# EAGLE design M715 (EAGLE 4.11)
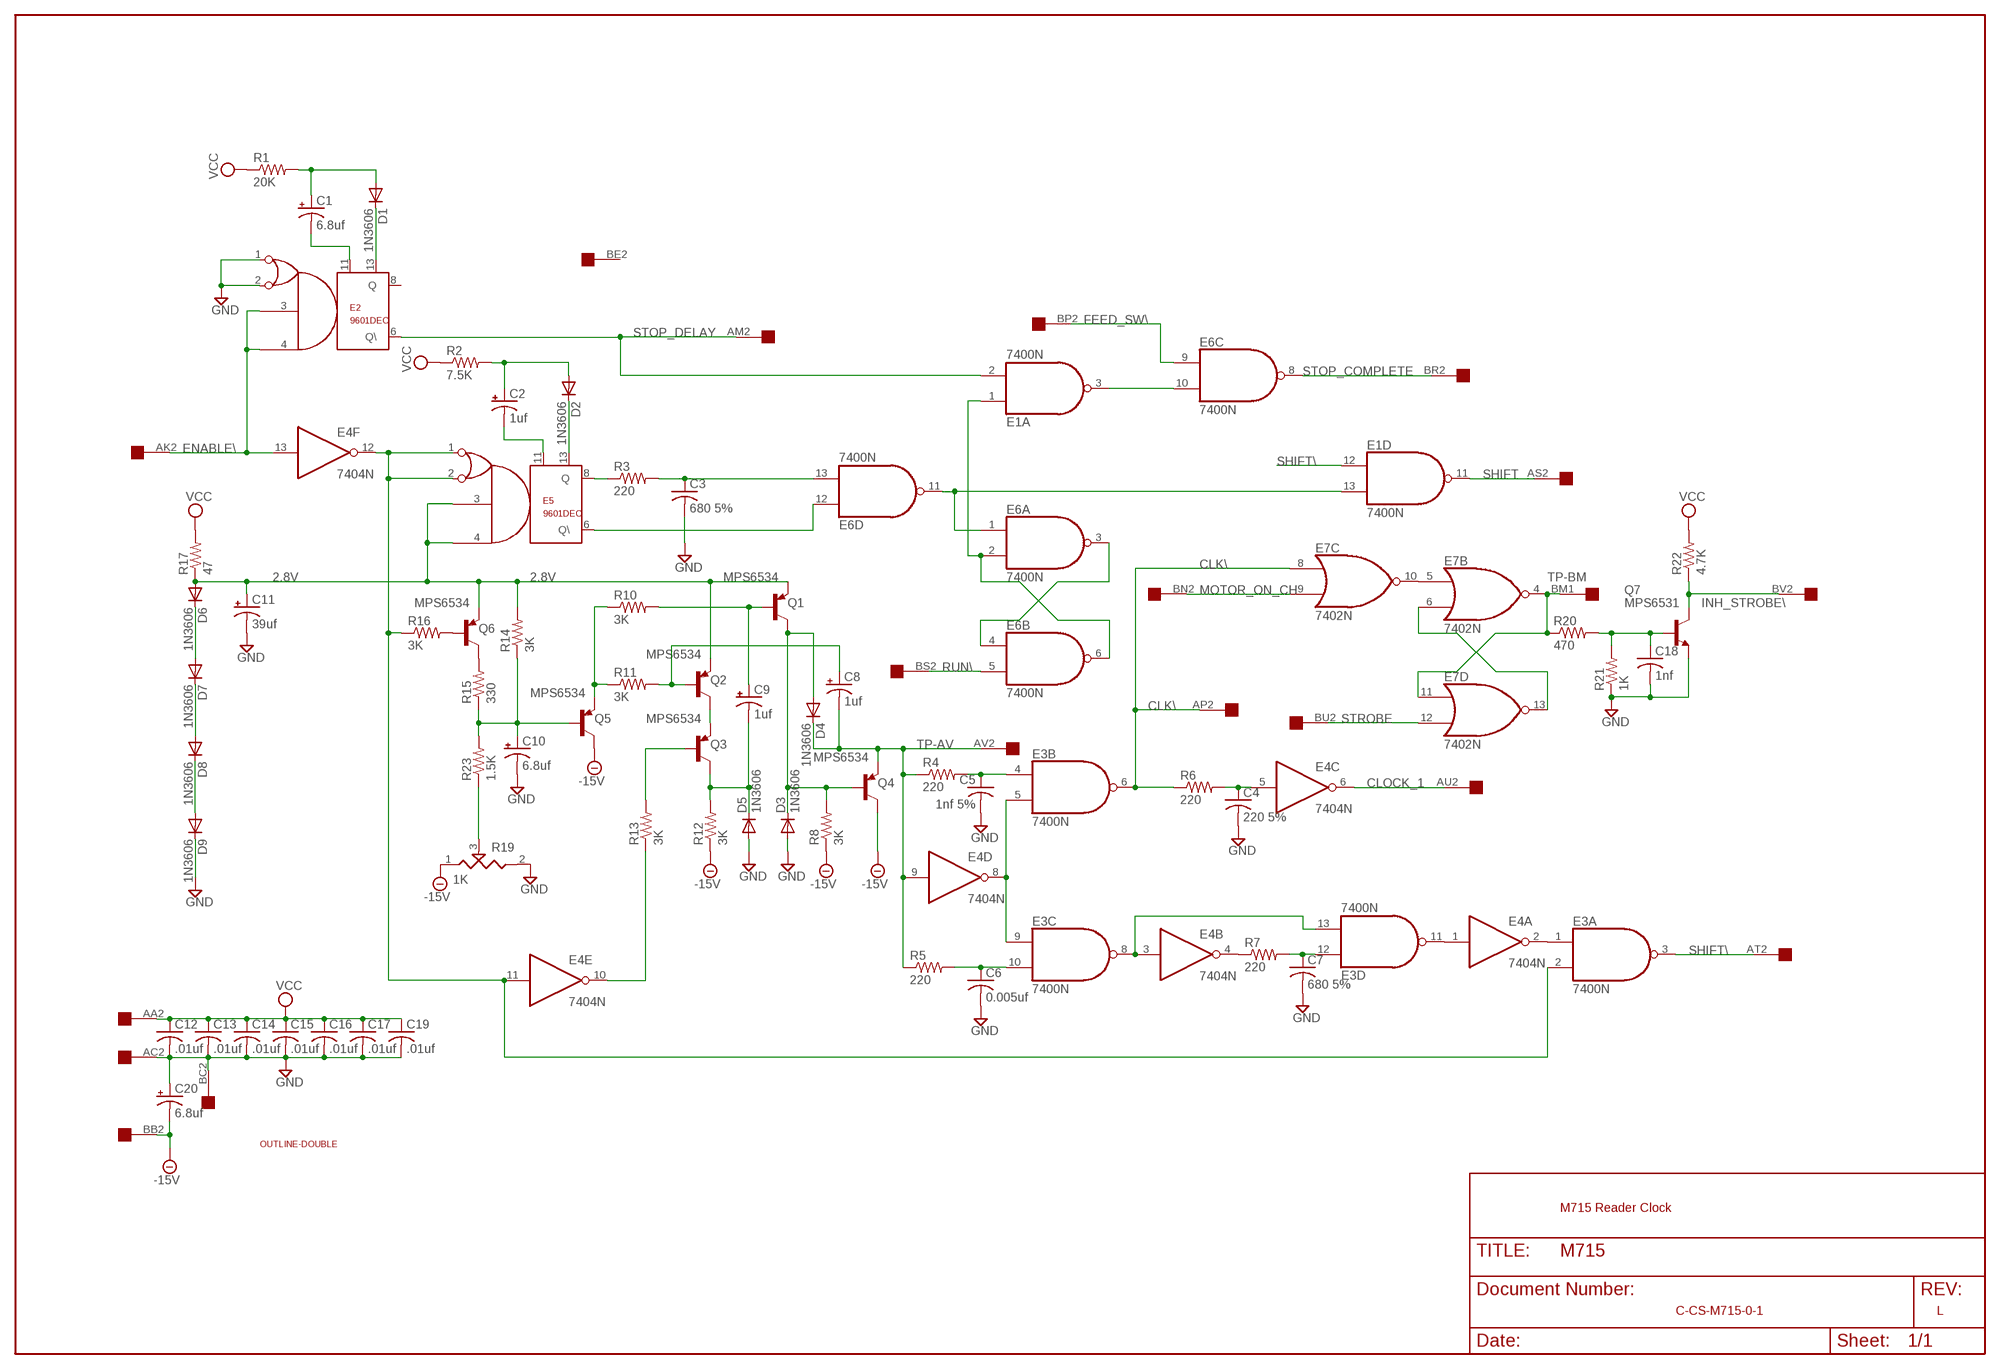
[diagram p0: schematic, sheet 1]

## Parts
C1  6.8uf  CPOL-USE22-6AXIAL  [E22-6]
C2  1uf  CPOL-USE15-5AXIAL  [E15-5]
C3  680 5%  C-US050-025X075  [C050-025X075]
C4  220 5%  C-US050-025X075  [C050-025X075]
C5  1nf 5%  C-US050-025X075  [C050-025X075]
C6  0.005uf  C-US050-025X075  [C050-025X075]
C7  680 5%  C-US050-025X075  [C050-025X075]
C8  1uf  CPOL-USE15-5AXIAL  [E15-5]
C9  1uf  CPOL-USE15-5AXIAL  [E15-5]
C10  6.8uf  CPOL-USE22-6AXIAL  [E22-6]
C11  39uf  CPOL-USE22-6AXIAL  [E22-6]
C12  .01uf  C-US050-025X075  [C050-025X075]
C13  .01uf  C-US050-025X075  [C050-025X075]
C14  .01uf  C-US050-025X075  [C050-025X075]
C15  .01uf  C-US050-025X075  [C050-025X075]
C16  .01uf  C-US050-025X075  [C050-025X075]
C17  .01uf  C-US050-025X075  [C050-025X075]
C18  1nf  C-US050-025X075  [C050-025X075]
C19  .01uf  C-US050-025X075  [C050-025X075]
C20  6.8uf  CPOL-USE22-6AXIAL  [E22-6]
D1  1N3606  1N4148  [DO35-10]
D2  1N3606  1N4148  [DO35-10]
D3  1N3606  1N4148  [DO35-10]
D4  1N3606  1N4148  [DO35-10]
D5  1N3606  1N4148  [DO35-10]
D6  1N3606  1N4148  [DO35-10]
D7  1N3606  1N4148  [DO35-10]
D8  1N3606  1N4148  [DO35-10]
D9  1N3606  1N4148  [DO35-10]
E1  7400N  [DIL14]
E2  9601DEC  [DIL14]
E3  7400N  [DIL14]
E4  7404N  [DIL14]
E5  9601DEC  [DIL14]
E6  7400N  [DIL14]
E7  7402N  [DIL14]
Q1  MPS6534  -PNP-TO92  [TO92]
Q2  MPS6534  -PNP-TO92  [TO92]
Q3  MPS6534  -PNP-TO92  [TO92]
Q4  MPS6534  -PNP-TO92  [TO92]
Q5  MPS6534  -PNP-TO92  [TO92]
Q6  MPS6534  -PNP-TO92  [TO92]
Q7  MPS6531  -NPN-TO92  [TO92]
R1  20K  R-US_0207/10  [0207/10]
R2  7.5K  R-US_0207/10  [0207/10]
R3  220  R-US_0207/10  [0207/10]
R4  220  R-US_0207/10  [0207/10]
R5  220  R-US_0207/10  [0207/10]
R6  220  R-US_0207/10  [0207/10]
R7  220  R-US_0207/10  [0207/10]
R8  3K  R-US_0207/10  [0207/10]
R10  3K  R-US_0207/10  [0207/10]
R11  3K  R-US_0207/10  [0207/10]
R12  3K  R-US_0207/10  [0207/10]
R13  3K  R-US_0207/10  [0207/10]
R14  3K  R-US_0207/10  [0207/10]
R15  330  R-US_0207/10  [0207/10]
R16  3K  R-US_0207/10  [0207/10]
R17  47  R-US_0207/10  [0207/10]
R19  1K  POTUS-TRIM  [PT-SPIN]
R20  470  R-US_0207/10  [0207/10]
R21  1K  R-US_0207/10  [0207/10]
R22  4.7K  R-US_0207/10  [0207/10]
R23  1.5K  R-US_0207/10  [0207/10]
U$1  DOUBLE  [EDGE-CON4]
U$2  OUTLINE-DOUBLE  [DOUBLE]

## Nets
2.8V: C11.+ D6.A E5.3 E5.4 Q1.1(E) Q2.1(E) Q6.1(E) R14.2 R17.1
-15V: C20.- Q4.3(C) Q5.3(C) R8.1 R12.1 R19.1 U$1.BB2
CLK\: E3.6(B:O) E7.8(C:I0) R6.1 U$1.AP2
CLOCK_1: E4.6(C:O) U$1.AU2
ENABLE\: E2.3 E2.4 E4.13(F:I) U$1.AK2
FEED_SW\: E6.9(C:I0) U$1.BP2
GND: C3.2 C4.2 C5.2 C6.2 C7.2 C10.- C11.- C12.2 C13.2 C14.2 C15.2 C16.2 C17.2 C18.2 C19.2 C20.+ D3.A D5.A D9.C E2.1 E2.2 Q7.1(E) R19.2 R21.1 U$1.AC2 U$1.BC2
INH_STROBE\: Q7.3(C) R22.1 U$1.BV2
MOTOR_ON_CH: E7.9(C:I1) U$1.BN2
N$1: E6.3(A:O) E6.4(B:I0)
N$2: E1.1(A:I0) E6.2(A:I1) E6.6(B:O)
N$3: E1.13(D:I1) E6.1(A:I0) E6.11(D:O)
N$4: E3.1(A:I0) E4.2(A:O)
N$5: E7.6(B:I1) E7.13(D:O)
N$6: E1.3(A:O) E6.10(C:I1)
N$7: Q6.2(B) R16.2
N$8: E7.5(B:I0) E7.10(C:O)
N$9: E3.2(A:I1) E4.11(E:I) E4.12(F:O) E5.1 E5.2 R16.1
N$10: E3.5(B:I1) E3.9(C:I0) E4.8(D:O)
N$11: E3.11(D:O) E4.1(A:I)
N$12: E3.8(C:O) E3.13(D:I1) E4.3(B:I)
N$13: C7.1 E3.12(D:I0) R7.2
N$14: E4.4(B:O) R7.1
N$15: R19.3 R23.1
N$16: C4.1 E4.5(C:I) R6.2
N$17: C18.1 Q7.2(B) R20.2 R21.2
N$18: C6.1 E3.10(C:I1) R5.2
N$19: C5.1 E3.4(B:I0) R4.2
N$20: D6.C D7.A
N$21: D7.C D8.A
N$22: D8.C D9.A
N$23: Q6.3(C) R15.2
N$24: C10.+ Q5.2(B) R14.1 R15.1 R23.2
N$26: Q5.1(E) R10.1 R11.1
N$27: Q2.3(C) Q3.1(E)
N$28: C8.+ Q2.2(B) R11.2
N$29: E4.10(E:O) R13.1
N$30: Q3.2(B) R13.2
N$31: C9.- D5.C Q3.3(C) R12.2
N$32: C9.+ Q1.2(B) R10.2
N$33: D3.C D4.A Q1.3(C) Q4.2(B) R8.2
N$35: D1.C E2.13
N$36: C1.- E2.11
N$37: C1.+ D1.A R1.2
N$38: D2.C E5.13
N$39: C2.- E5.11
N$40: C2.+ D2.A R2.2
N$41: E5.6(Q\) E6.12(D:I0)
N$42: E5.8(Q) R3.1
N$43: C3.1 E6.13(D:I1) R3.2
RUN\: E6.5(B:I1) U$1.BS2
SHIFT: E1.11(D:O) U$1.AS2
SHIFT\: E1.12(D:I0) E3.3(A:O) U$1.AT2
STOP_COMPLETE: E6.8(C:O) U$1.BR2
STOP_DELAY: E1.2(A:I1) E2.6(Q\) U$1.AM2
STROBE: E7.12(D:I1) U$1.BU2
TP-AV: C8.- D4.C E4.9(D:I) Q4.1(E) R4.1 R5.1 U$1.AV2
TP-BM: E7.4(B:O) E7.11(D:I0) R20.1 U$1.BM1
VCC: C12.1 C13.1 C14.1 C15.1 C16.1 C17.1 C19.1 R1.1 R2.1 R17.2 R22.2 U$1.AA2
Unconnected: E1.4(B:I0) E1.5(B:I1) E1.6(B:O) E1.8(C:O) E1.9(C:I0) E1.10(C:I1) E2.8(Q) E7.1(A:O) E7.2(A:I0) E7.3(A:I1) U$1.AA1 U$1.AB1 U$1.AB2 U$1.AC1 U$1.AD1 U$1.AD2 U$1.AE1 U$1.AE2 U$1.AF1 U$1.AF2 U$1.AH1 U$1.AH2 U$1.AJ1 U$1.AJ2 U$1.AK1 U$1.AL1 U$1.AL2 U$1.AM1 U$1.AN1 U$1.AN2 U$1.AP1 U$1.AR1 U$1.AR2 U$1.AS1 U$1.AT1 U$1.AU1 U$1.AV1 U$1.BA1 U$1.BA2 U$1.BB1 U$1.BC1 U$1.BD1 U$1.BD2 U$1.BE1 U$1.BE2 U$1.BF1 U$1.BF2 U$1.BH1 U$1.BH2 U$1.BJ1 U$1.BJ2 U$1.BK1 U$1.BK2 U$1.BL1 U$1.BL2 U$1.BM2 U$1.BN1 U$1.BP1 U$1.BR1 U$1.BS1 U$1.BT1 U$1.BT2 U$1.BU1 U$1.BV1

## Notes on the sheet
- M715 Reader Clock
- C-CS-M715-0-1 | L

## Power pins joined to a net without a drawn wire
GND: E1.7(P:GND) E2.7(GND) E3.7(P:GND) E4.7(P:GND) E5.7(GND) E6.7(P:GND) E7.7(P:GND)
VCC: E1.14(P:VCC) E2.14(VCC) E3.14(P:VCC) E4.14(P:VCC) E5.14(VCC) E6.14(P:VCC) E7.14(P:VCC)

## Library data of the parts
C1 C2 C8-C11 C20 = rcl:CPOL-US: POLARIZED CAPACITOR, American symbol
C3-C7 C12-C19 = rcl:C-US: CAPACITOR, American symbol
D1-D9 = diode:1N4148: DIODE
E1 E3 E6 = 74xx-us:74*00: Quad 2-input NAND gate
E2 E5 = dec-con:9601
E4 = 74xx-us:74*04: Hex INVERTER
E7 = 74xx-us:74*02: Quad 2-input NOR gate
Q1-Q6 = transistor:*-PNP-: PNP Transistror
Q7 = transistor:*-NPN-: NPN Transistror
R1-R8 R10-R17 R20-R23 = rcl:R-US_: RESISTOR, American symbol
R19 = discrete:POTUS-TRIM
U$1 = dec-con:DOUBLE: Double-Height DEC board
U$2 = dec-con:OUTLINE-*: Board outlines for DEC boards.

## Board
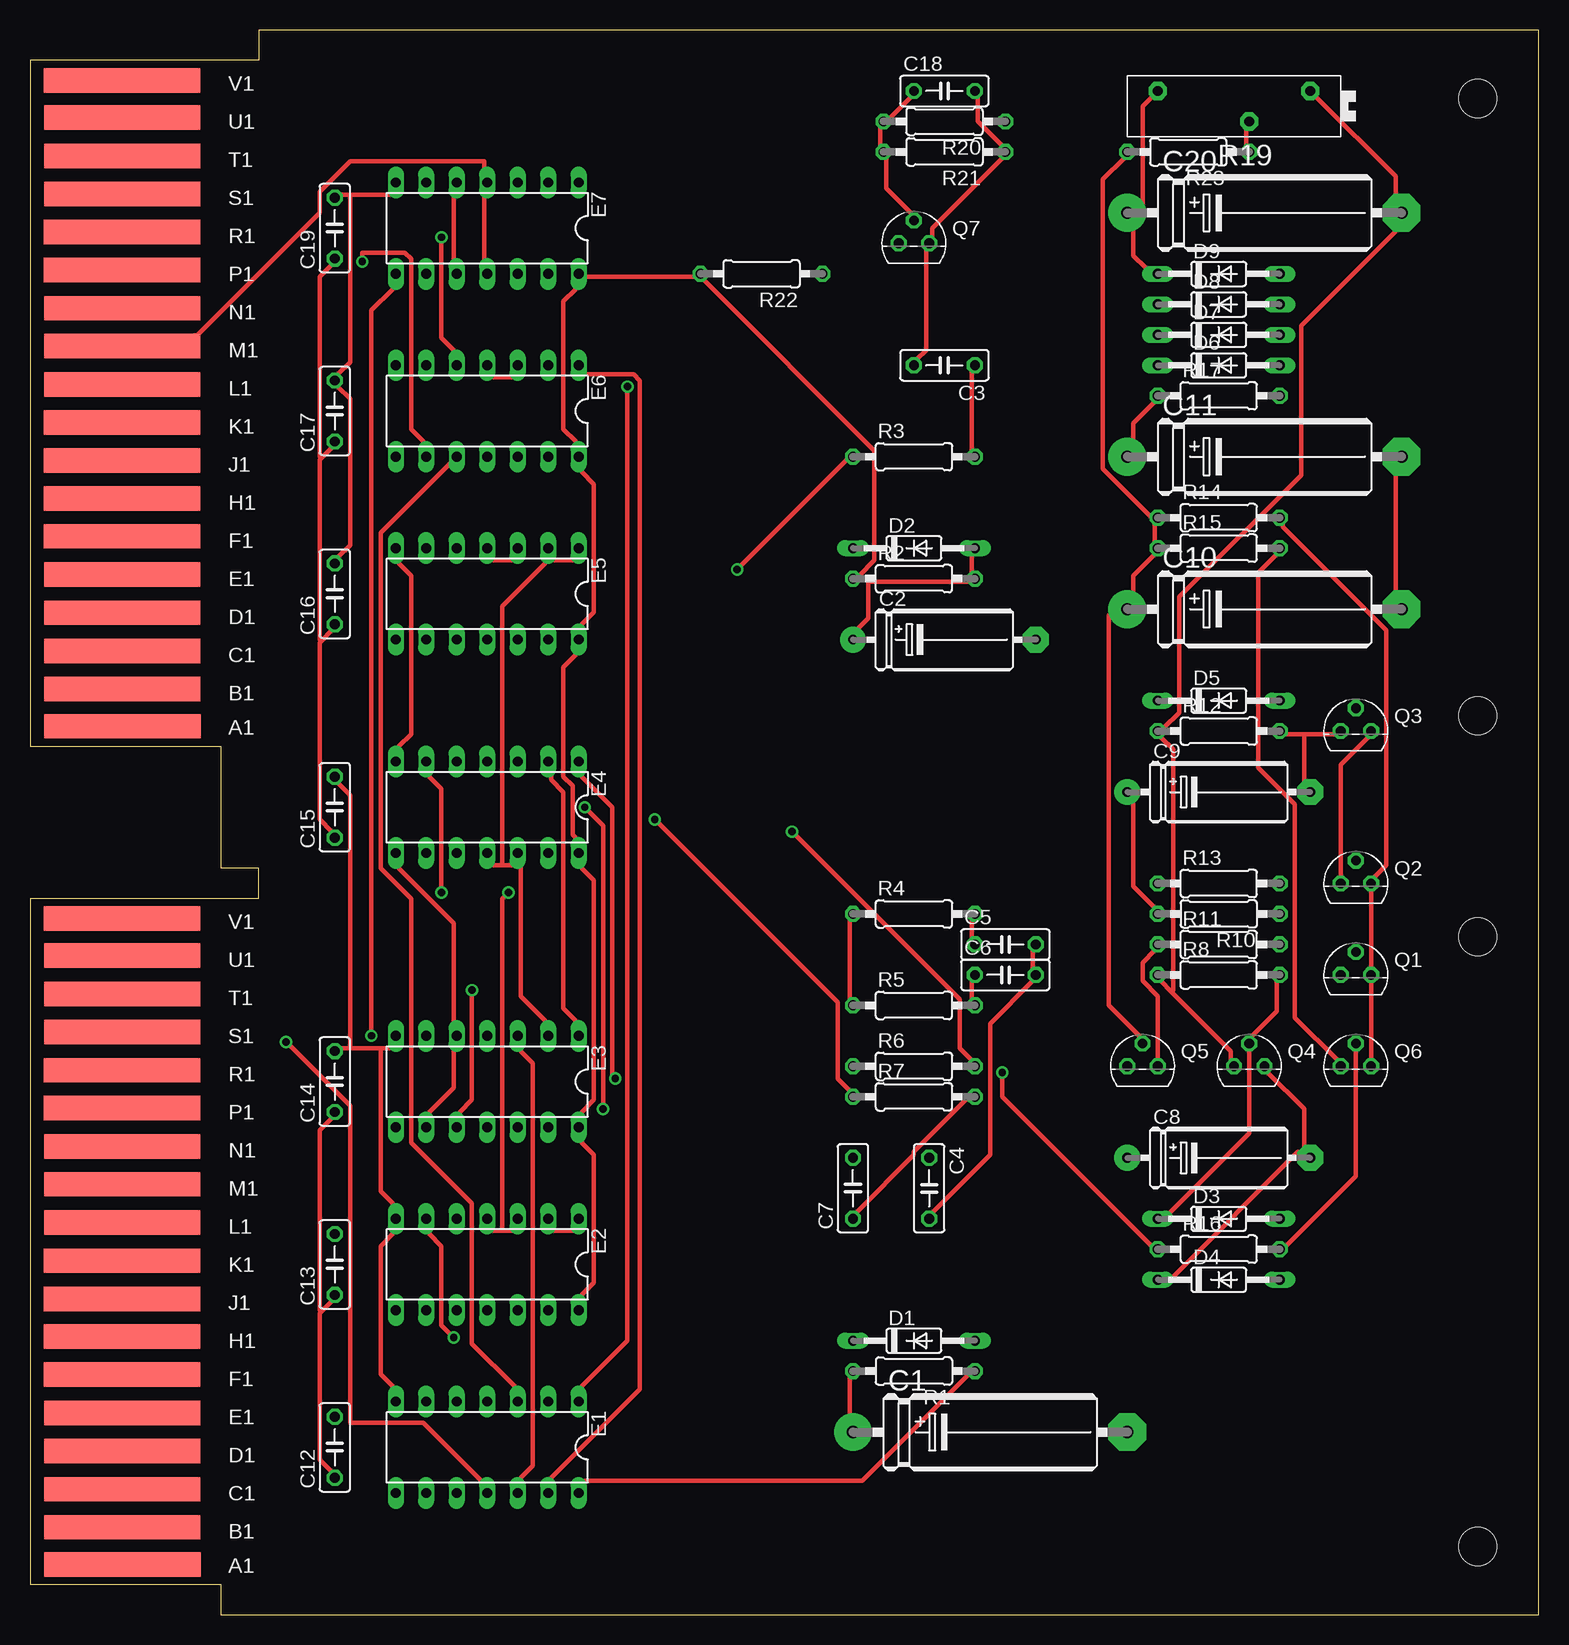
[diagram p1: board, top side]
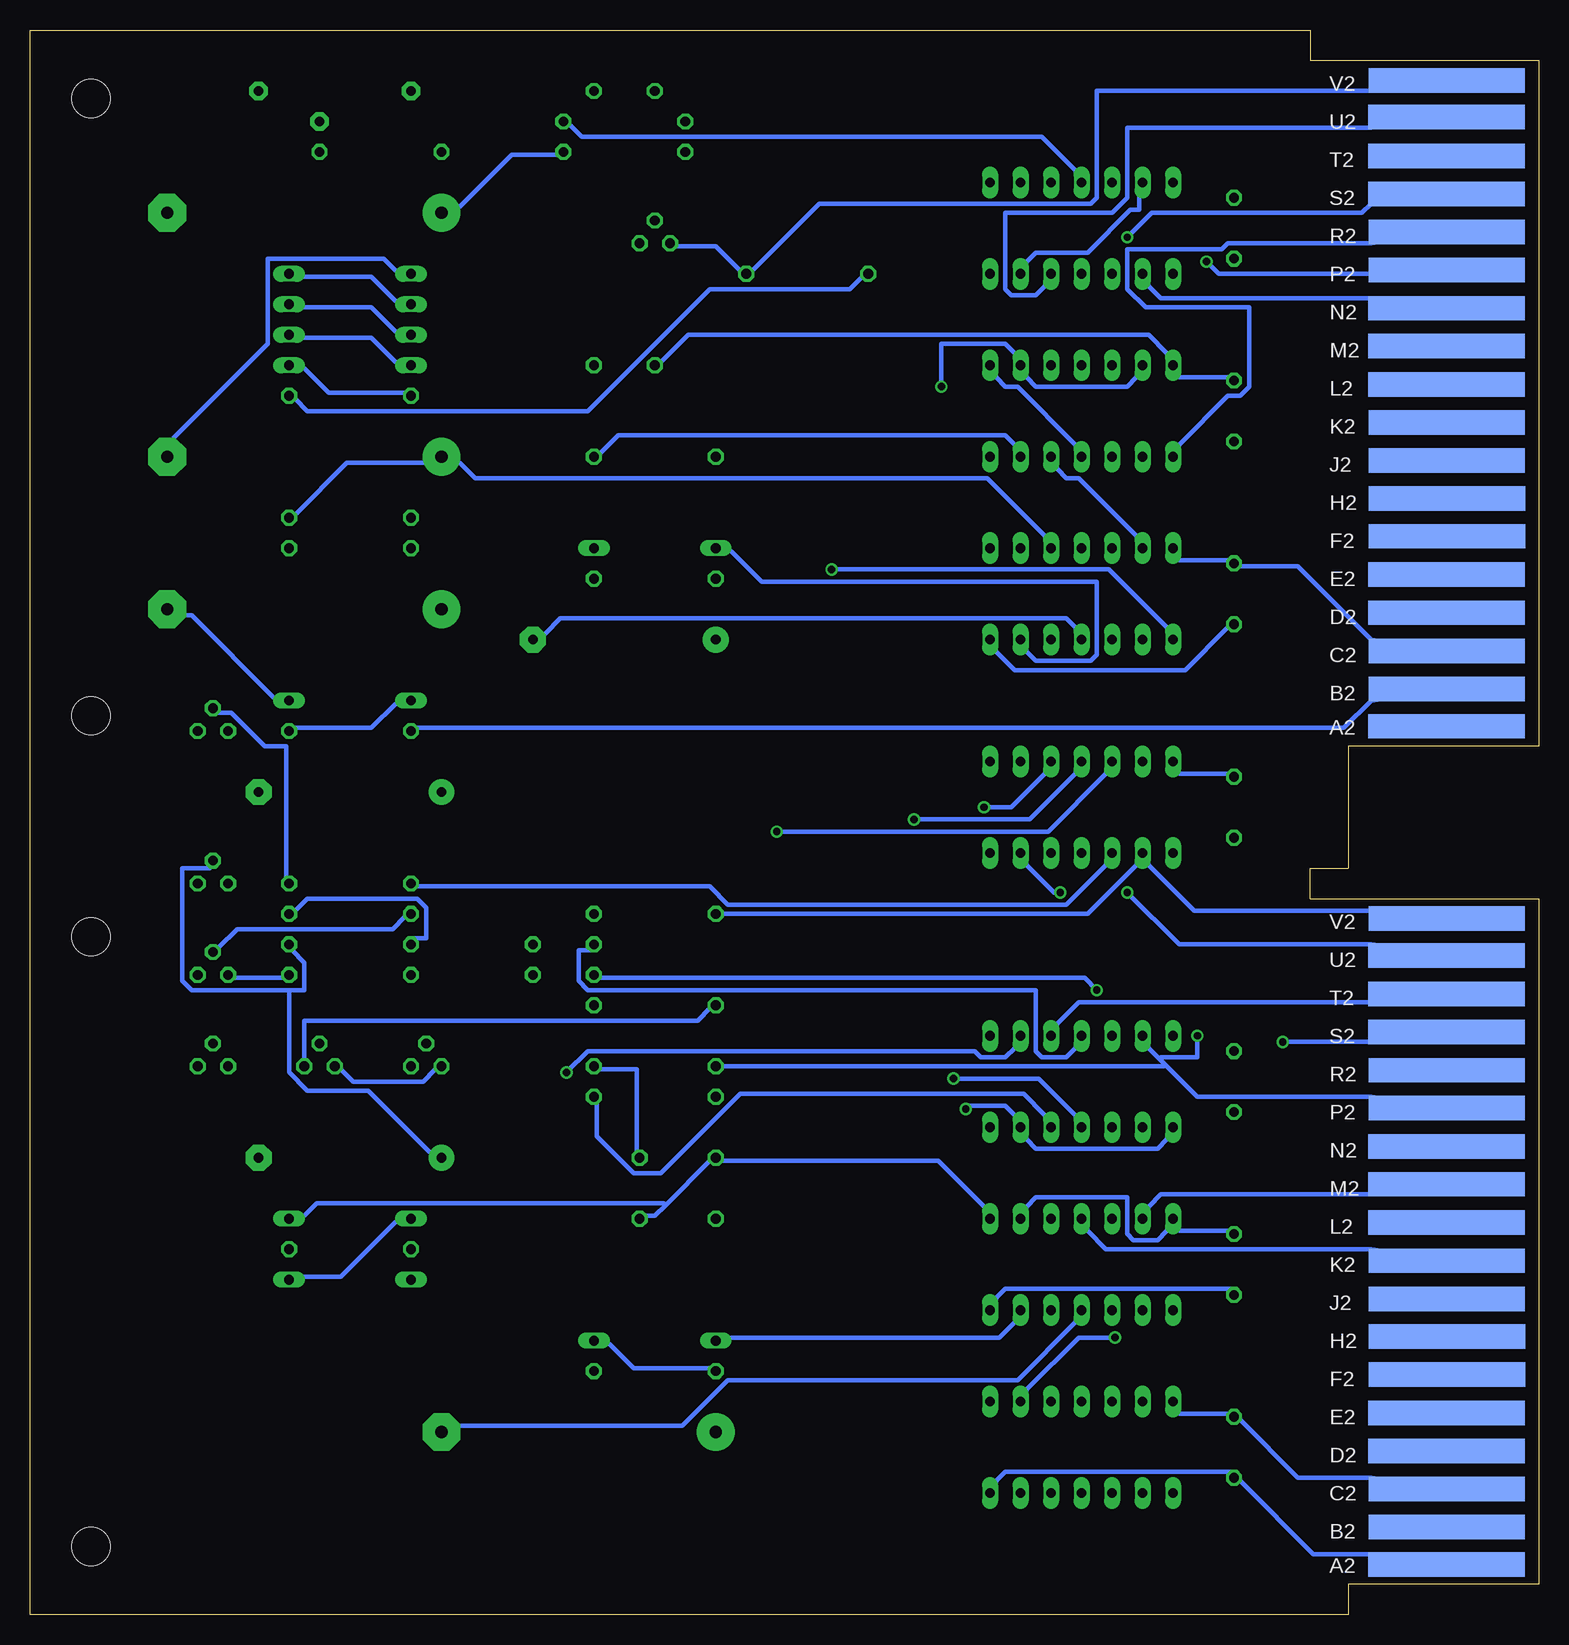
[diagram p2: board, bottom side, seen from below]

Size 125.73 x 132.08 mm. Coordinates in mm from the lower left corner, seen from the top.
Copper layers (1*16): Top 0.035mm / dielectric 1.5mm / Bottom 0.035mm
Design rules "15mils": minimum track width 15mil, minimum drill 24mil, track to track 15mil, track to pad 10mil, pad to pad 10mil, via to via 10mil, smd to smd 10mil, copper to edge 25mil, drill to drill 10mil, minimum pad ring 10mil, minimum via ring 8mil, stop-mask expansion 0mil, vias tented up to drill 0mil, thermal gap 10mil

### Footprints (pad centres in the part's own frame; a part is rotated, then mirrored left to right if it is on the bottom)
E22-6 = drill 1.016 pad 3.15 round: + -11.43,0 | drill 1.016 pad 3.15 octagon: - 11.43,0
E15-5 = drill 0.813 pad 2.159 round: + -7.62,0 | drill 0.813 pad 2.159 octagon: - 7.62,0
C050-025X075 = drill 0.813 octagon: 1 -2.54,0; 2 2.54,0
DO35-10 = drill 0.813 long: A 5.08,0; C -5.08,0
DIL14 = drill 0.813 long: 1 -7.62,-3.81; 2 -5.08,-3.81; 3 -2.54,-3.81; 4 0,-3.81; 5 2.54,-3.81; 6 5.08,-3.81; 7 7.62,-3.81; 8 7.62,3.81; 9 5.08,3.81; 10 2.54,3.81; 11 0,3.81; 12 -2.54,3.81; 13 -5.08,3.81; 14 -7.62,3.81
TO92 = drill 0.813 octagon: 1 1.27,0; 2 0,1.905; 3 -1.27,0
0207/10 = drill 0.813 octagon: 1 -5.08,0; 2 5.08,0
PT-SPIN = drill 0.813 pad 1.524 octagon: 1 -6.35,-1.27; 2 6.35,-1.27; 3 -1.27,1.27
EDGE-CON4 = smd 13.017 x 2.032: AA1 7.709,4.207; AB1 7.684,7.312; AC1 7.684,10.474; AD1 7.684,13.665; AE1 7.693,16.84; AF1 7.668,20.041; AH1 7.668,23.19; AJ1 7.668,26.34; AK1 7.668,29.515; AL1 7.693,32.69; AM1 7.693,35.89; AN1 7.693,39.04; AP1 7.668,42.24; AR1 7.668,45.39; AS1 7.693,48.565; AT1 7.693,51.74; AU1 7.693,54.94; AV1 7.668,58.026; BA1 7.709,74.057; BB1 7.684,77.162; BC1 7.684,80.324; BD1 7.684,83.515; BE1 7.693,86.69; BF1 7.668,89.891; BH1 7.668,93.04; BJ1 7.668,96.19; BK1 7.668,99.365; BL1 7.693,102.54; BM1 7.693,105.74; BN1 7.693,108.89; BP1 7.668,112.09; BR1 7.668,115.24; BS1 7.693,118.415; BT1 7.693,121.59; BU1 7.693,124.79; BV1 7.668,127.876 | smd 13.017 x 2.032 bottom: AA2 7.69,4.207; AB2 7.668,7.328; AC2 7.668,10.49; AD2 7.693,13.665; AE2 7.693,16.84; AF2 7.642,20.041; AH2 7.642,23.19; AJ2 7.668,26.34; AK2 7.668,29.515; AL2 7.693,32.69; AM2 7.693,35.89; AN2 7.693,39.04; AP2 7.668,42.24; AR2 7.668,45.39; AS2 7.693,48.565; AT2 7.693,51.74; AU2 7.693,54.966; AV2 7.668,58.026; BA2 7.69,74.057; BB2 7.668,77.178; BC2 7.668,80.34; BD2 7.693,83.515; BE2 7.693,86.69; BF2 7.642,89.891; BH2 7.642,93.04; BJ2 7.668,96.19; BK2 7.668,99.365; BL2 7.693,102.54; BM2 7.693,105.74; BN2 7.693,108.89; BP2 7.668,112.09; BR2 7.668,115.24; BS2 7.693,118.415; BT2 7.693,121.59; BU2 7.693,124.816; BV2 7.668,127.876
DOUBLE = hole 3.175: 120.65,56.515; 120.65,5.715; 120.65,74.93; 120.65,126.365

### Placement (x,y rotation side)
C1  80.01,15.24 0 top
C2  76.2,81.28 0 top
C3  76.2,104.14 180 top
C4  74.93,35.56 270 top
C5  81.28,55.88 0 top
C6  81.28,53.34 0 top
C7  68.58,35.56 90 top
C8  99.06,38.1 0 top
C9  99.06,68.58 0 top
C10  102.87,83.82 0 top
C11  102.87,96.52 0 top
C12  25.4,13.97 90 top
C13  25.4,29.21 90 top
C14  25.4,44.45 90 top
C15  25.4,67.31 90 top
C16  25.4,85.09 90 top
C17  25.4,100.33 90 top
C18  76.2,127 0 top
C19  25.4,115.57 90 top
C20  102.87,116.84 0 top
D1  73.66,22.86 0 top
D2  73.66,88.9 0 top
D3  99.06,33.02 0 top
D4  99.06,27.94 0 top
D5  99.06,76.2 0 top
D6  99.06,104.14 0 top
D7  99.06,106.68 0 top
D8  99.06,109.22 0 top
D9  99.06,111.76 0 top
E1  38.1,13.97 180 top
E2  38.1,29.21 180 top
E3  38.1,44.45 180 top
E4  38.1,67.31 180 top
E5  38.1,85.09 180 top
E6  38.1,100.33 180 top
E7  38.1,115.57 180 top
Q1  110.49,53.34 0 top
Q2  110.49,60.96 0 top
Q3  110.49,73.66 0 top
Q4  101.6,45.72 0 top
Q5  92.71,45.72 0 top
Q6  110.49,45.72 0 top
Q7  73.66,114.3 0 top
R1  73.66,20.32 180 top
R2  73.66,86.36 0 top
R3  73.66,96.52 0 top
R4  73.66,58.42 0 top
R5  73.66,50.8 0 top
R6  73.66,45.72 0 top
R7  73.66,43.18 0 top
R8  99.06,53.34 0 top
R10  99.06,58.42 180 top
R11  99.06,55.88 0 top
R12  99.06,73.66 0 top
R13  99.06,60.96 0 top
R14  99.06,91.44 0 top
R15  99.06,88.9 0 top
R16  99.06,30.48 0 top
R17  99.06,101.6 0 top
R19  100.33,125.73 180 top
R20  76.2,124.46 180 top
R21  76.2,121.92 180 top
R22  60.96,111.76 180 top
R23  96.52,121.92 180 top
U$1  0,0 0 top
U$2  0,0 0 top

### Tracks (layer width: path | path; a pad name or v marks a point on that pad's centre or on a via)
2.8V
  Top 0.381: Q6.1 111.76,46.23 111.76,52.83 Q1.1 111.76,53.85 111.76,60.45 Q2.1 112.01,61.47 113.03,62.48 113.03,82.04 104.39,90.68 104.39,90.93 R14.2 | E5.4 38.61,87.88 40.13,87.88 E5.3 | R17.1 93.73,101.09 91.95,99.31 91.95,98.04 C11.+
  Bottom 0.381: R14.2 103.63,91.69 99.31,96.01 92.96,96.01 C11.+ 89.92,96.01 88.65,94.74 45.97,94.74 41.15,89.92 E5.3 | D6.A 102.87,103.89 100.84,101.85 94.49,101.85 R17.1
-15V
  Top 0.381: R19.1 107.19,126.49 113.79,119.89 113.79,118.36 C20.- 113.79,115.32 105.92,107.44 105.92,95 95.76,84.84 95.76,75.18 94.49,73.91 R12.1 94.23,73.15 95.25,72.14 95.25,52.07 95.12,51.94 | 95.12,51.94 100.08,46.99 100.08,46.23 Q4.3 | 95.12,51.94 94.23,52.83 R8.1
  Bottom 0.381: Q5.3 91.95,45.47 92.96,44.45 98.81,44.45 99.82,45.47 Q4.3 | U$1.BB2 13.97,76.2 16.26,73.91 93.47,73.91 R12.1
CLK\  (via drill 0.61)
  Top 0.381: v28.45,48.26 28.45,108.71 30.23,110.49 E7.8
  Bottom 0.381: 31.12,45.85 28.45,43.18 13.97,43.18 U$1.AP2 | 31.12,45.85 31.62,46.35 | 31.62,46.35 32.51,47.24 E3.6 | R6.1 68.07,45.72 31.24,45.72 31.12,45.85 | v28.45,48.26 28.45,46.48 31.5,46.48 31.62,46.35
CLOCK_1  (via drill 0.61)
  Top 0.381: v34.29,60.2 34.29,68.83 33.27,69.85 E4.6
  Bottom 0.381: v34.29,60.2 29.97,55.88 13.97,55.88 U$1.AU2
ENABLE\  (via drill 0.61)
  Top 0.381: 39.37,32 40.13,32 E2.3 | 39.37,32 38.61,32 E2.4 | v39.88,60.2 39.37,59.69 39.37,32
  Bottom 0.381: v39.88,60.2 40.39,60.2 42.67,62.48 E4.13 | U$1.AK2 13.97,30.48 36.07,30.48 37.59,32 E2.4
FEED_SW\  (via drill 0.61)
  Top 0.381: v27.69,112.78 27.69,113.54 31.24,113.54 31.75,113.03 31.75,98.81 32.77,97.79 E6.9
  Bottom 0.381: v27.69,112.78 26.67,111.76 13.97,111.76 U$1.BP2
GND
  Top 0.381: C11.- 113.79,95 113.79,85.34 C10.- | D9.C 92.96,112.27 91.95,113.28 91.95,115.32 C20.+ 92.71,117.6 92.71,125.73 93.47,126.49 R19.2 | C18.2 78.99,126.49 78.99,124.46 81.03,122.43 R21.1 81.03,121.41 75.18,115.57 75.18,114.81 Q7.1 74.68,113.79 74.68,105.41 73.91,104.65 C3.2 | 26.67,118.36 29.97,118.36 E7.7 | 26.67,118.36 25.91,118.36 C19.2 | 26.67,118.36 26.67,104.39 25.65,103.38 C17.2 25.65,102.36 26.67,101.35 26.67,89.15 25.65,88.14 C16.2 | E4.7 30.73,72.39 31.75,73.41 31.75,86.61 30.73,87.63 E5.7 | 29.21,47.24 29.97,47.24 E3.7 | 29.21,47.24 26.67,47.24 | 26.67,47.24 25.91,47.24 C14.2 | 29.21,47.24 29.21,35.31 30.23,34.29 E2.7 30.23,31.75 29.21,30.73 29.21,20.07 30.23,19.05 E1.7 | C5.2 83.57,55.37 83.57,53.85 C6.2 83.57,52.83 80.01,49.28 80.01,38.35 75.18,33.53 C4.2 | E2.2 43.69,32 45.21,32 E2.1 | 26.67,47.24 26.67,68.33 25.65,69.34 C15.2
  Bottom 0.381: D5.A 105.41,76.45 112.27,83.31 112.78,83.31 C10.- | C20.+ 89.92,117.35 85.6,121.67 81.79,121.67 R21.1 | C11.- 113.79,98.04 105.92,105.92 105.92,113.03 96.27,113.03 95.25,112.01 D9.C | C17.2 25.91,103.12 29.97,103.12 E6.7 30.99,105.16 32.51,106.68 70.87,106.68 73.15,104.39 C3.2 | C15.2 25.91,70.1 29.97,70.1 E4.7 | E5.7 29.97,87.88 25.91,87.88 C16.2 24.89,87.38 20.07,87.38 13.97,81.28 U$1.BC2 | C13.2 25.91,32 29.97,32 E2.7 30.99,32 31.75,31.24 33.78,31.24 34.29,31.75 34.29,34.8 41.91,34.8 42.67,34.04 E2.2 | E1.7 29.97,16.76 25.91,16.76 C12.2 24.89,16.26 20.07,11.43 13.97,11.43 U$1.AC2 | 72.77,34.16 73.66,33.27 74.42,33.27 C4.2 | 72.77,34.16 69.09,37.85 C7.2 68.07,37.85 50.04,37.85 46.23,34.04 E2.1 | D3.A 102.87,33.27 101.85,34.29 72.9,34.29 72.77,34.16
INH_STROBE\
  Bottom 0.381: Q7.3 71.88,114.05 68.58,114.05 66.55,112.01 R22.1 65.53,112.01 59.94,117.6 37.34,117.6 36.83,118.11 36.83,127 13.97,127 U$1.BV2
MOTOR_ON_CH
  Bottom 0.381: E7.9 32.51,110.74 31.5,109.73 13.97,109.73 U$1.BN2
N$1
  Top 0.381: E6.4 38.61,103.12 40.13,103.12 E6.3
N$2  (via drill 0.61)
  Top 0.381: v49.78,102.36 49.78,22.86 45.97,19.05 E1.1
  Bottom 0.381: E6.6 33.53,103.12 34.29,102.36 41.91,102.36 42.67,103.12 E6.2 43.69,105.16 44.45,105.92 49.78,105.92 v49.78,102.36
N$3
  Top 0.381: E1.13 43.43,11.43 50.8,18.8 50.8,102.87 50.29,103.38 46.23,103.38 E6.1
  Bottom 0.381: E6.11 38.61,97.54 43.43,102.36 44.45,102.36 45.21,103.12 E6.1
N$4
  Top 0.381: E3.1 45.47,49.53 44.45,50.55 44.45,68.58 43.43,69.6 43.43,69.85 E4.2
N$5
  Bottom 0.381: E7.6 33.27,118.11 33.27,117.09 34.04,117.09 37.59,113.54 41.91,113.54 42.67,112.78 E7.13
N$6
  Top 0.381: E1.3 40.39,19.05 36.83,22.61 36.83,34.29 31.75,39.37 31.75,59.69 29.21,62.23 29.21,90.17 35.05,96.01 E6.10
N$7
  Top 0.381: R16.2 104.65,30.73 110.49,36.58 110.49,46.99 Q6.2
N$8
  Top 0.381: E7.10 35.31,113.03 35.31,118.11 E7.5
N$9  (via drill 0.61)
  Top 0.381: E5.1 45.21,87.88 43.69,87.88 E5.2 42.93,87.63 39.37,84.07 39.37,62.48 | 39.37,62.48 40.13,62.48 E4.12 40.89,62.23 40.89,51.56 42.93,49.53 E3.2 | 39.37,62.48 38.61,62.48 E4.11 | v81.03,45.21 81.03,43.18 93.47,30.73 R16.1
  Bottom 0.381: v81.03,45.21 79.25,46.99 46.99,46.99 46.48,46.48 44.45,46.48 43.69,47.24 E3.2
N$10
  Top 0.381: E3.9 33.27,41.91 35.31,43.94 35.31,46.99 E3.5 35.31,49.53 35.31,57.66 30.73,62.23 E4.8
N$11  (via drill 0.61)
  Top 0.381: v48.77,44.7 48.51,44.96 48.51,67.31 45.97,69.85 E4.1
  Bottom 0.381: v48.77,44.7 41.66,44.7 38.61,41.66 E3.11
N$12  (via drill 0.61)
  Top 0.381: v46.23,67.31 47.75,65.79 v47.75,42.16
  Bottom 0.381: E3.8 30.99,39.62 31.75,38.86 41.91,38.86 42.67,39.62 E3.13 43.69,41.66 44.45,42.42 47.5,42.42 v47.75,42.16 | v46.23,67.31 43.94,67.31 41.15,70.1 E4.3
N$13
  Top 0.381: C7.1 68.83,33.53 73.66,38.35 73.66,38.61 78.23,43.18 R7.2
  Bottom 0.381: E3.12 41.15,41.66 42.93,43.43 66.55,43.43 73.15,36.83 75.44,36.83 78.49,39.88 78.49,42.67 R7.2
N$14  (via drill 0.61)
  Top 0.381: v52.07,66.29 67.31,51.05 67.31,44.7 68.33,43.69 R7.1
  Bottom 0.381: v52.07,66.29 42.42,66.29 38.61,70.1 E4.4
N$15
  Top 0.381: R23.1 101.35,122.43 101.35,123.95 R19.3
N$16  (via drill 0.61)
  Top 0.381: v63.5,65.28 77.47,51.31 77.47,47.24 78.49,46.23 R6.2
  Bottom 0.381: v63.5,65.28 40.89,65.28 36.07,70.1 E4.5 | C4.1 75.18,38.61 75.18,45.47 78.23,45.47 R6.2
N$17
  Top 0.381: Q7.2 73.41,116.84 71.37,118.87 71.37,121.41 R21.2 70.87,122.43 70.87,123.95 R20.2 71.63,124.71 73.41,126.49 C18.1
N$18  (via drill 0.61)
  Top 0.381: v36.83,52.07 36.83,42.93 35.81,41.91 E3.10 | R5.2 78.49,51.31 78.49,52.83 C6.1
  Bottom 0.381: v36.83,52.07 37.85,53.09 78.23,53.09 C6.1
N$19
  Top 0.381: R4.2 78.49,57.91 78.49,56.39 C5.1
  Bottom 0.381: E3.4 38.61,47.24 39.37,46.48 41.4,46.48 41.91,46.99 41.91,52.07 79.25,52.07 80.01,52.83 80.01,55.37 78.99,55.37 C5.1
N$20
  Bottom 0.381: D6.C 95.25,104.39 97.28,106.43 102.87,106.43 D7.A
N$21
  Bottom 0.381: D7.C 95.25,106.93 97.28,108.97 102.87,108.97 D8.A
N$22
  Bottom 0.381: D8.C 95.25,109.47 97.28,111.51 102.87,111.51 D9.A
N$23
  Top 0.381: Q6.3 108.97,46.23 105.41,49.78 105.41,67.56 102.36,70.61 102.36,86.87 103.89,88.39 R15.2
N$24
  Top 0.381: R23.2 91.19,121.41 89.41,119.63 89.41,95.5 93.47,91.44 R14.1 93.73,90.93 93.73,89.41 R15.1 93.73,88.39 91.95,86.61 91.95,85.34 C10.+ 89.92,83.31 89.92,50.8 92.46,48.26 Q5.2
N$26
  Top 0.381: Q5.1 93.98,46.23 93.98,51.56 92.71,52.83 92.71,54.36 93.73,55.37 R11.1
  Bottom 0.381: R10.1 103.63,58.67 102.62,59.69 93.47,59.69 92.71,58.93 92.71,56.39 93.73,56.39 R11.1
N$27
  Top 0.381: Q2.3 109.22,61.47 109.22,70.87 111.51,73.15 Q3.1
N$28
  Bottom 0.381: 104.14,52.07 112.27,52.07 113.03,52.83 113.03,62.23 110.74,62.23 Q2.2 | 104.14,52.07 102.87,52.07 102.87,54.36 103.89,55.37 R11.2 | 104.14,52.07 104.14,45.21 102.62,43.69 97.54,43.69 92.46,38.61 C8.+
N$29
  Bottom 0.381: E4.10 36.07,62.48 39.37,59.18 67.56,59.18 69.09,60.71 93.47,60.71 R13.1
N$30
  Bottom 0.381: R13.2 104.39,61.47 104.39,72.39 106.17,72.39 108.97,75.18 109.98,75.18 Q3.2
N$31
  Top 0.381: 106.17,73.41 108.71,73.41 Q3.3 | 106.17,73.41 104.65,73.41 R12.2 | 106.17,73.41 106.17,69.6 C9.-
  Bottom 0.381: D5.C 95.25,75.95 97.28,73.91 103.63,73.91 R12.2
N$32
  Top 0.381: R10.2 93.73,58.93 91.95,60.71 91.95,67.56 C9.+
  Bottom 0.381: Q1.2 109.98,55.63 108.46,57.15 95.5,57.15 94.49,58.17 R10.2
N$33
  Top 0.381: R8.2 103.89,52.83 103.89,50.29 101.85,48.26 Q4.2 101.6,46.99 101.6,40.13 95,33.53 D3.C
  Bottom 0.381: Q1.3 108.71,53.09 104.65,53.09 R8.2 | D3.C 95.25,32.77 99.82,28.19 102.87,28.19 D4.A
N$35
  Bottom 0.381: E2.13 43.69,24.38 44.96,23.11 67.31,23.11 D1.C
N$36
  Bottom 0.381: E2.11 38.61,24.38 43.43,19.56 67.56,19.56 71.37,15.75 89.92,15.75 C1.-
N$37
  Top 0.381: R1.2 68.33,19.81 68.33,16.76 C1.+
  Bottom 0.381: D1.A 77.47,22.61 75.44,20.57 69.09,20.57 R1.2
N$38
  Bottom 0.381: E5.13 42.67,80.26 41.91,79.5 37.34,79.5 36.83,80.01 36.83,86.11 64.77,86.11 67.31,88.65 D2.C
N$39
  Bottom 0.381: E5.11 38.61,82.3 39.37,83.06 81.53,83.06 82.8,81.79 C2.-
N$40
  Top 0.381: D2.A 78.49,88.39 78.49,86.87 R2.2 78.23,86.11 69.85,86.11 69.85,83.06 69.09,82.3 C2.+
N$41
  Bottom 0.381: E5.6 33.53,89.92 38.35,94.74 39.37,94.74 40.13,95.5 E6.12
N$42  (via drill 0.61)
  Top 0.381: v58.93,87.12 68.07,96.27 R3.1
  Bottom 0.381: v58.93,87.12 35.81,87.12 30.99,82.3 E5.8
N$43
  Top 0.381: C3.1 78.49,103.63 78.49,97.03 R3.2
  Bottom 0.381: E6.13 43.69,97.54 44.45,98.3 76.71,98.3 78.23,96.77 R3.2
RUN\  (via drill 0.61)
  Top 0.381: v34.29,114.81 34.29,106.43 35.31,105.41 E6.5
  Bottom 0.381: v34.29,114.81 32.26,116.84 14.73,116.84 13.97,117.6 U$1.BS2
SHIFT  (via drill 0.61)
  Top 0.381: v21.34,47.75 26.67,42.42 26.67,16 32.77,16 37.59,11.18 E1.11
  Bottom 0.381: v21.34,47.75 13.97,47.75 U$1.AS2
SHIFT\
  Top 0.381: E1.12 40.89,11.43 41.91,12.45 41.91,45.97 40.89,46.99 E3.3
  Bottom 0.381: U$1.AT2 13.97,51.05 38.35,51.05 40.13,49.28 E3.3
STOP_COMPLETE
  Bottom 0.381: E6.8 29.97,97.54 25.91,101.6 24.89,101.6 24.13,102.36 24.13,108.97 32.77,108.97 34.29,110.49 34.29,113.79 26.42,113.79 25.91,114.3 13.97,114.3 U$1.BR2
STOP_DELAY  (via drill 0.61)
  Top 0.381: v35.31,23.11 34.29,24.13 34.29,30.73 33.27,31.75 E2.6
  Bottom 0.381: E2.6 32.51,34.04 31.5,35.05 13.97,35.05 U$1.AM2 | v35.31,23.11 38.35,23.11 42.67,18.8 E1.2
STROBE
  Bottom 0.381: E7.12 41.15,110.74 41.91,109.98 43.94,109.98 44.45,110.49 44.45,116.84 35.56,116.84 34.29,118.11 34.29,123.95 13.97,123.95 U$1.BU2
TP-AV
  Top 0.381: D4.C 95.25,28.19 105.66,38.61 C8.- 106.17,39.12 106.17,42.16 103.12,45.21 Q4.1 | R5.1 68.33,51.31 68.33,57.91 R4.1
  Bottom 0.381: U$1.AV2 13.97,58.67 28.7,58.67 32.51,62.48 E4.9 33.53,62.48 37.59,58.42 68.07,58.42 R4.1 | Q4.1 102.87,46.23 102.87,49.53 70.1,49.53 69.09,50.55 R5.1
TP-BM
  Top 0.381: E7.11 37.85,113.03 37.85,118.11 E7.4 37.85,120.65 37.85,121.16 26.67,121.16 24.13,118.62 24.13,116.84 13.97,106.68 U$1.BM1
  Bottom 0.381: R20.1 80.77,124.21 79.76,123.19 41.4,123.19 38.61,120.4 E7.4
VCC
  Top 0.381: E2.14 45.97,26.67 46.99,27.69 46.99,38.35 45.97,39.37 E3.14 45.97,41.91 46.99,42.93 46.99,61.21 45.97,62.23 E4.14 45.47,64.77 45.21,65.02 45.21,69.09 44.45,69.85 44.45,78.99 45.47,80.01 E5.14 45.97,82.55 46.99,83.57 46.99,94.23 45.97,95.25 E6.14 45.47,97.79 44.45,98.81 44.45,109.47 45.47,110.49 E7.14 46.23,111.51 55.37,111.51 R22.2 56.13,111.25 70.36,97.03 70.36,87.88 69.09,86.61 R2.1 | 24.26,25.27 24.13,25.15 24.13,12.95 25.15,11.94 C12.1 | 24.26,25.27 25.15,26.16 C13.1 | C14.1 25.15,41.4 24.13,40.39 24.13,25.4 24.26,25.27 | R1.1 78.23,20.07 69.34,11.18 46.23,11.18 E1.14 | 24.26,81.15 25.15,82.04 C16.1 | 24.26,81.15 24.13,81.03 24.13,66.29 25.15,65.28 C15.1 | 24.26,96.39 24.13,96.27 24.13,81.28 24.26,81.15 | 24.26,96.39 25.15,97.28 C17.1 | C19.1 25.15,112.52 24.13,111.51 24.13,96.52 24.26,96.39
  Bottom 0.381: U$1.AA2 13.97,5.08 18.8,5.08 24.89,11.18 C12.1 25.65,11.94 44.45,11.94 45.21,11.18 E1.14 | E2.14 45.21,26.42 44.45,27.18 25.65,27.18 C13.1 | R17.2 103.63,101.35 102.62,100.33 79.25,100.33 69.09,110.49 57.4,110.49 56.39,111.51 R22.2 | C16.1 25.91,82.3 29.46,78.74 43.69,78.74 45.21,80.26 E5.14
